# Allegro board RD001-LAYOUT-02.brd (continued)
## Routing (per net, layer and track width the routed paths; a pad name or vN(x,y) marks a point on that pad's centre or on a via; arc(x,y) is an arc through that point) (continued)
SIGN322: length 40.1
  TOP w0.3: 147.27,102.56 147.94,102.56 150.5,100 152.8,100 v2(153.2,100.4)
  TOP w0.55: IC5.6 147.27,102.56
  BOTTOM w0.3: 167.66,113 169.4,113 169.81,113.05 ; v2(153.2,100.4) 153.2,103.7 157,107.5 157,110.8 157.8,111.6 169.8,111.6 170,111.8 170,112.33 ; 167.43,113.23 167.43,114.7 167.37,114.76 166.85,115.3
  BOTTOM w0.55: 169.81,113.05 D22.C 170,112.33
  BOTTOM w0.8: 167.43,113.23 D46.A 167.66,113
  BOTTOM w1.1: D47.C 166.85,115.3
SIGN323: length 2.5
  BOTTOM w0.3: 163.2,113 164.77,113
  BOTTOM w0.92: R136.1 163.2,113
  BOTTOM w1.1: 164.77,113 D46.C
SIGN324: length 1.5
  BOTTOM w0.3: 163.16,115.3 164.29,115.3
  BOTTOM w0.8: 164.29,115.3 D47.A
  BOTTOM w0.92: R137.1 163.16,115.3
SIGN325: length 12.3
  TOP w0.3: 163.29,71.15 164.15,71.15 164.6,70.7 165.75,70.7 ; D44.A 164.97,67.69 164.97,66.47 162.64,64.14 162.64,63.77 ; 166.12,70.42 165.78,69.67 165.78,68.73
  TOP w0.55: 162.64,62.95 IC4.6 162.64,63.77 ; 163.29,71.15 D25.C
  TOP w0.8: D44.A 165.78,68.73
  TOP w1.1: 165.75,70.7 D45.C 166.12,70.42
SIGN326: length 1.6
  TOP w0.3: 168.29,70.7 168.81,70.7 169.5,70.8
  TOP w0.8: D45.A 168.29,70.7
  TOP w0.92: 169.5,70.8 R135.1
SIGN327: length 2
  TOP w0.3: 168.33,68.5 169.6,68.5
  TOP w0.92: 169.6,68.5 R134.1
  TOP w1.1: D44.C 168.33,68.5
SIGN336: length 2.4
  BOTTOM w0.3: 233,91.5 234.6,91.5
  BOTTOM w0.92: 234.6,91.5 R20.1
  BOTTOM w1.1: D53.C 233,91.5
SIGN337: length 1.6
  BOTTOM w0.3: 233.44,93.8 234.73,93.8
  BOTTOM w0.8: D54.A 233.44,93.8
  BOTTOM w0.92: 234.73,93.8 R213.1
SIGN338: length 3.6
  BOTTOM w0.3: 232.75,108.4 234.6,108.4 234.85,108.65 234.85,109.31
  BOTTOM w0.92: 234.85,109.31 R18.1
  BOTTOM w1.1: D51.C 232.75,108.4
SIGN339: length 2.6
  BOTTOM w0.3: R212.1 234.2,112 233.32,111.12 D52.A
SIGN340: length 52.2
  TOP w0.3: 233.47,117.42 233.47,117.89 v2(233.5,118.3) ; 233.88,123.31 234.44,123.31 v2(234.7,123.05) ; v2(213.1,121.6) TP21.1
  TOP w0.5: Q12.4 233.47,117.42 ; Q11.4 233.88,123.31
  CONDUCTIVE4 w0.2: v2(234.7,123.05) 234.2,123.55 215.05,123.55 v2(213.1,121.6)
  CONDUCTIVE4 w0.6: v2(233.5,118.3) 233.5,121.85 v2(234.7,123.05) ; v2(233.5,118.3) 236.65,118.3 v2(237.15,118.8) ; v2(233.5,118.3) 233.5,114.15 234.35,113.3 v2(238.3,113.3)
  BOTTOM w0.3: R216.1 v2(237.15,118.8) ; 237.55,109.31 237.55,108.61 R19.2 ; v2(238.3,113.3) 237.98,112.98 237.55,112.44
  BOTTOM w0.5: 237.55,111.34 237.55,110.09
  BOTTOM w0.92: 237.55,110.09 R18.2 237.55,109.31 ; 237.55,111.34 R212.2 237.55,112.44
SIGN341: length 2.4
  BOTTOM w0.3: 224.6,39.3 224.6,37.78
  BOTTOM w0.92: R24.1 224.6,39.3
  BOTTOM w1.1: 224.6,37.78 D57.C
SIGN342: length 1.5
  BOTTOM w0.3: 222.3,39.35 222.3,38.25
  BOTTOM w0.8: 222.3,38.25 D58.A
  BOTTOM w0.92: R215.1 222.3,39.35
SIGN343: length 45.2
  TOP w0.3: v2(243.85,68.9) 241.9,68.9 ; v2(231.6,74.2) 233.22,74.2 233.47,73.95 233.47,73.39
  TOP w0.5: 233.47,73.39 Q7.4
  TOP w2.1: 241.9,68.9 TP22.1
  CONDUCTIVE4 w0.6: v2(243.96,60.95) 244.9,61.89 244.9,67.85 v2(243.85,68.9) 242.65,70.1 v2(237.15,70.1) 233.9,70.1 231.6,72.4 v2(231.6,74.2) 225.95,79.85 v2(225.95,79.95)
  BOTTOM w0.3: 242.55,64.43 242.55,63.27 ; 236.41,70.1 v2(237.15,70.1) ; 242.71,62.7 243.4,62.7 243.72,62.38 R22.2 ; v2(225.95,79.95) 225.97,80.36 225.97,81.11 ; v2(243.96,60.95) 243.96,61.72
  BOTTOM w0.5: Q8.4 225.97,81.11
  BOTTOM w0.72: R218.1 236.41,70.1 ; 243.96,61.72 R22.2
  BOTTOM w0.92: 242.71,62.7 R23.2 242.55,63.27 ; R214.2 242.55,64.43
SIGN344: length 2.5
  BOTTOM w0.3: 238.03,62.7 239.6,62.7
  BOTTOM w0.92: 239.6,62.7 R23.1
  BOTTOM w1.1: D55.C 238.03,62.7
SIGN345: length 1.5
  BOTTOM w0.3: 238.51,65 239.64,65
  BOTTOM w0.8: D56.A 238.51,65
  BOTTOM w0.92: 239.64,65 R214.1
SIGN351: length 1.8
  BOTTOM w0.3: 233.8,119.5 234.26,119.5 R216.2
  BOTTOM w0.5: Q25.4 233.8,119.5
SIGN352: length 1.8
  BOTTOM w0.3: 233.8,100.8 234.16,100.8 R217.2
  BOTTOM w0.5: Q14.4 233.8,100.8
SIGN353: length 1.8
  BOTTOM w0.3: 233.8,69.39 234.25,69.39 R218.2
  BOTTOM w0.5: Q28.4 233.8,69.39
SIGN354: length 1.5
  BOTTOM w0.3: 233.98,53.8 234.36,53.8 234.9,53.8
  BOTTOM w0.5: Q10.4 233.98,53.8
  BOTTOM w0.72: 234.9,53.8 R219.2
SIGN355: length 142.1
  BOTTOM w1: D19.C 158.8,93 157.2,91.4 150,91.4 ; 150,91.4 149.05,90.45 ; 150,91.4 149.05,91.4 147.95,92.5 ; 150,91.4 149.05,92.35
  BOTTOM w3: Q5.D 142.95,115.25 145.85,112.35 145.85,96.75 147.95,94.65 Q3.D 147.95,77.05 151.09,73.91 155.46,73.91 156.96,72.41 167.72,72.41 171.15,68.98 171.15,51.92 189.02,34.05 T4.1
SIGN356: length 7.5
  BOTTOM w0.45: 221.6,22.69 221.6,21.32 D14.A ; T4.5 217.44,21.3 220.93,21.3
  BOTTOM w0.55: D14.A 220.93,21.3
  BOTTOM w0.72: R9.2 221.6,22.69
SIGN361:
  vias: v5(222.55,83.2) v5(230.05,71.3) v5(230.05,71.3)
SIGN364: length 52.2
  TOP w0.15: 76.1,51.7 R138.1 ; L12.1 106.6,32.2 ; 96.72,49 95.92,49.8 IC20.4 ; C64.2 102.35,42.8
  TOP w5: 76.1,51.7 78.54,51.7 83.24,47 88.58,47 90.58,49 96.72,49 102.35,43.37 102.35,36.45 106.6,32.2
SIGN366: length 5.3
  TOP w0.5: 129.6,64.13 129.6,66.25 HS1.1
  TOP w0.72: R220.2 129.6,64.13
SIGN369: length 6
  TOP w0.45: R221.2 166.46,42.7 HS2.1
SIGN371: length 5.3
  TOP w0.5: HS3.1 117.3,45.15 117.3,43.03
  TOP w0.72: R222.2 117.3,43.03
SIGN373: length 6.4
  TOP w0.5: 173.7,89.67 173.7,87.4 HS4.1
  TOP w0.72: R223.2 173.7,89.67
VREF: length 66.1
  TOP w0.45: v2(258.6,17.5) v2(259.85,17.5) 259.85,13.61 259.24,13 259.24,11.87
  TOP w0.5: 259.38,11.6 260.6,11.6 261.2,11 v2(261.2,10.2) v2(261.2,8.9) 261.2,8.6 260.6,8 259.45,8
  TOP w0.72: 259.24,11.87 R207.2 259.38,11.6 ; R58.2 259.45,8
  CONDUCTIVE3 w1: 245.9,7.3 245.9,7.9 ; 245.9,7.3 245.3,7.9 ; 245.9,7.3 245.9,6.35 244.65,5.1 v2(244.3,5.1) ; 245.9,7.9 245.9,8.5 ; 245.9,7.9 245.3,7.9 ; v2(244.3,7.9) 245.3,7.9 ; 245.3,7.9 245.9,8.5 ; 245.9,8.5 245.9,12.8 248.95,15.85 255.35,15.85 257,17.5 v2(258.6,17.5) ; 259.85,16.25 v2(259.85,17.5) v2(258.6,17.5) ; 259.85,16.25 v2(258.6,17.5) ; 259.85,16.25 259.85,14.05 261.2,12.7 v2(261.2,10.2) v2(261.2,8.9)
  BOTTOM w0.3: R57.2 259.84,10.2 v2(261.2,10.2) v2(261.2,8.9) 261.2,7.95 ; R210.2 v2(244.3,5.1) ; R211.2 v2(244.3,7.9)
  BOTTOM w0.45: 255.06,16.31 255.06,16.76 C99.2 254.78,17.55 256.6,17.55 257.13,17.44 ; v2(259.85,17.5) v2(258.6,17.5) 258.19,17.44 257.46,17.44
  BOTTOM w0.6: 255.06,16.31 IC10.1
  BOTTOM w0.72: 257.46,17.44 R44.2 257.13,17.44 ; 261.2,7.95 R62.2
VREF_PFC: length 40
  TOP w0.3: 154.32,3.64 154.86,3.6 v2(155.4,3.6)
  TOP w0.72: 154.32,3.64 R177.2
  CONDUCTIVE3 w0.5: v2(146.05,4.95) v2(147.3,4.95) 154.05,4.95 v2(155.4,3.6) 156.75,4.95 156.75,15.15 154.65,17.25 v2(153.9,17.25)
  BOTTOM w0.3: R171.2 157.39,17.25 v2(153.9,17.25) ; v2(147.3,4.95) 147.67,5.12 148.26,5.12 ; v2(155.4,3.6) 154.76,3.6 R97.2 ; C42.2 149.15,5.88 149.82,5.88
  BOTTOM w0.4: 149.82,5.88 IC3.13
  BOTTOM w0.45: 148.26,5.12 C42.2
  BOTTOM w0.5: v2(147.3,4.95) v2(146.05,4.95)

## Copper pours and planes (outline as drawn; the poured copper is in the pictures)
P12V on BOTTOM: 273.7,55.25 268.82,60.13 268.79,60.18 268.77,60.24 268.77,68.75 268.82,68.86 268.93,68.9 300.24,68.9 300.3,68.89 300.34,68.86 301.86,67.34 301.89,67.3 301.9,67.24 301.9,40.22 301.89,40.15 301.81,40.01 301.71,39.91 301.51,39.73 301.35,39.55 301.01,38.35 301.55,37.23 301.55,37.22 303.19,35.59 303.32,35.51 303.4,35.5 303.7,35.5 303.85,35.46 303.96,35.35 304,35.2 303.96,35.05 303.85,34.94 303.7,34.9 301.56,34.9 301.5,34.91 301.46,34.94 300.73,35.67 300.46,35.83 300.3,35.85 293.96,35.85 293.79,35.82 293.64,35.72 292.87,34.94 292.82,34.91 292.76,34.9 289.9,34.9 289.75,34.94 289.64,35.05 289.6,35.2 289.6,36.48 289.56,36.63 289.51,36.69 286.29,39.91 286.19,39.98 286.08,40 273.85,40 273.74,40.04 273.7,40.15 ; 18 cut-outs
P12V on CONDUCTIVE3: 272.4,68.8 272.43,68.87 272.5,68.9 300.24,68.9 300.3,68.89 300.34,68.86 301.86,67.34 301.89,67.29 301.9,67.24 301.9,41.76 301.89,41.7 301.86,41.66 300.24,40.04 300.19,40.01 300.14,40 276.86,40 276.8,40.01 276.76,40.04 274.23,42.57 274.21,42.6 274.2,42.64 274.2,56.55 272.43,58.32 272.41,58.35 272.4,58.39 ; 3 cut-outs
VCC3R3_1 on TOP: 205.04,14.6 204.93,14.64 204.89,14.75 204.89,16.19 204.9,16.25 204.93,16.29 205.34,16.71 205.39,16.74 205.45,16.75 206.45,16.75 206.56,16.71 206.6,16.6 206.6,14.75 206.56,14.64 206.45,14.6
VCC12R0_1 on CONDUCTIVE4: 208.05,6.7 207.98,6.73 207.95,6.8 207.95,7.46 207.96,7.5 207.98,7.53 209.32,8.87 209.35,8.89 209.39,8.9 211.25,8.9 211.32,8.87 211.35,8.8 211.35,6.8 211.32,6.73 211.25,6.7
VCC12R0_2 on TOP: 230.55,89.25 230.43,89.27 230.33,89.35 230.3,89.39 230.29,89.45 230.29,90.6 230.33,90.75 230.44,90.86 230.59,90.9 231.8,90.9 231.95,90.86 232.06,90.75 232.1,90.6 232.1,89.55 232.06,89.4 231.95,89.29 231.8,89.25
VCC12R0_2 on TOP: 279.25,4.2 279.1,4.24 278.99,4.35 278.95,4.5 278.95,5.75 278.99,5.9 279.1,6.01 279.25,6.05 281.64,6.05 281.74,6.03 281.82,5.98 281.88,5.89 281.9,5.79 281.9,4.52 281.89,4.45 281.81,4.31 281.79,4.29 281.73,4.24 281.58,4.2
VCC12R0_2 on CONDUCTIVE3: 279.29,3.95 279.25,3.96 279.22,3.98 277.64,5.56 277.57,5.62 277.48,5.64 277.42,5.68 277.4,5.74 277.4,5.95 277.44,6.1 277.55,6.21 277.7,6.25 280.85,6.25 281,6.21 281.11,6.1 281.15,5.95 281.15,4.25 281.11,4.1 281,3.99 280.85,3.95
CONN002 on TOP: 180.75,71.2 184.75,71.2
CONN002 on TOP: 140.91,76.8 140.91,82.2 144.09,82.2 144.09,76.8
CONN002 on BOTTOM: 142.99,76.8 142.96,76.81 142.93,76.82 140.93,78.82 140.92,78.84 140.91,78.87 140.91,82.12 140.93,82.18 140.99,82.2 144.01,82.2 144.07,82.18 144.09,82.12 144.09,76.88 144.07,76.82 144.01,76.8
CONN002 on CONDUCTIVE4: 163.6,77 163.45,77.04 163.34,77.15 163.3,77.3 163.3,79.5 162.2,82.01 159.61,82.89 159.59,82.89 159.45,82.9 159.3,82.9 148.15,82.9 148.1,82.9 145.6,81.96 144.55,79.5 144.55,77.9 144.51,77.75 144.4,77.64 144.25,77.6 140.95,77.6 140.8,77.64 140.69,77.75 140.65,77.9 140.65,82.67 140.66,82.7 140.68,82.74 147.25,89.31 147.32,89.36 147.47,89.4 154.9,89.4 161.26,95.76 161.32,95.81 161.47,95.85 167.38,95.85 167.45,95.84 167.59,95.76 167.91,95.44 167.96,95.38 168,95.23 168,81.46 168,81.43 167.55,80.5 167.4,79.5 167.4,77.3 167.36,77.15 167.25,77.04 167.1,77
CONN003 on TOP: 180.75,56.1 184.75,56.1
CONN003 on BOTTOM: 179.75,54.1 179.75,58.1 184.75,58.1 184.75,54.1
CONN003 on BOTTOM: 179.75,92 179.75,96 184.75,96 184.75,92
CONN004 on TOP (solid shape): 270.8,55.91 271.29,55.78 271.75,55.56 272.16,55.27 272.52,54.91 272.81,54.5 273.03,54.04 273.16,53.55 273.2,53.05 273.2,47.55 273.16,47.05 273.03,46.56 272.81,46.1 272.52,45.69 272.16,45.33 271.75,45.04 271.29,44.82 270.8,44.69 270.3,44.65 269.8,44.69 269.31,44.82 268.85,45.04 268.44,45.33 268.08,45.69 267.79,46.1 267.57,46.56 267.44,47.05 267.4,47.55 267.4,53.05 267.44,53.55 267.57,54.04 267.79,54.5 268.08,54.91 268.44,55.27 268.85,55.56 269.31,55.78 269.8,55.91 270.3,55.95
CONN004 on TOP (solid shape): 275.3,107.51 275.79,107.38 276.25,107.16 276.66,106.87 277.02,106.51 277.31,106.1 277.53,105.64 277.66,105.15 277.7,104.65 277.7,99.15 277.66,98.65 277.53,98.16 277.31,97.7 277.02,97.29 276.66,96.93 276.25,96.64 275.79,96.42 275.3,96.29 274.8,96.25 274.3,96.29 273.81,96.42 273.35,96.64 272.94,96.93 272.58,97.29 272.29,97.7 272.07,98.16 271.94,98.65 271.9,99.15 271.9,104.65 271.94,105.15 272.07,105.64 272.29,106.1 272.58,106.51 272.94,106.87 273.35,107.16 273.81,107.38 274.3,107.51 274.8,107.55
CONN004 on BOTTOM (solid shape): 270.8,55.91 271.29,55.78 271.75,55.56 272.16,55.27 272.52,54.91 272.81,54.5 273.03,54.04 273.16,53.55 273.2,53.05 273.2,47.55 273.16,47.05 273.03,46.56 272.81,46.1 272.52,45.69 272.16,45.33 271.75,45.04 271.29,44.82 270.8,44.69 270.3,44.65 269.8,44.69 269.31,44.82 268.85,45.04 268.44,45.33 268.08,45.69 267.79,46.1 267.57,46.56 267.44,47.05 267.4,47.55 267.4,53.05 267.44,53.55 267.57,54.04 267.79,54.5 268.08,54.91 268.44,55.27 268.85,55.56 269.31,55.78 269.8,55.91 270.3,55.95
CONN004 on BOTTOM (solid shape): 275.3,107.51 275.79,107.38 276.25,107.16 276.66,106.87 277.02,106.51 277.31,106.1 277.53,105.64 277.66,105.15 277.7,104.65 277.7,99.15 277.66,98.65 277.53,98.16 277.31,97.7 277.02,97.29 276.66,96.93 276.25,96.64 275.79,96.42 275.3,96.29 274.8,96.25 274.3,96.29 273.81,96.42 273.35,96.64 272.94,96.93 272.58,97.29 272.29,97.7 272.07,98.16 271.94,98.65 271.9,99.15 271.9,104.65 271.94,105.15 272.07,105.64 272.29,106.1 272.58,106.51 272.94,106.87 273.35,107.16 273.81,107.38 274.3,107.51 274.8,107.55
CONN004 on TOP: outline of 190 points within 251.6,44.65 303.5,123.18
CONN004 on BOTTOM: outline of 197 points within 251,44.65 298.36,123.15
CONN004 on CONDUCTIVE3: 258.29,44.1 258.25,44.11 258.22,44.13 253.53,48.82 253.51,48.85 253.5,48.89 253.5,114.05 251.63,115.92 251.61,115.95 251.6,115.99 251.6,123.1 251.63,123.17 251.7,123.2 258.16,123.2 258.2,123.19 258.23,123.17 265.4,116 294.96,116 295,115.99 295.03,115.97 297.47,113.53 297.49,113.5 297.5,113.46 297.5,84 298.92,82.58 298.94,82.55 298.95,82.51 298.95,73 298.92,72.93 298.85,72.9 273.44,72.9 273.4,72.91 273.37,72.93 271.7,74.6 271.67,74.67 271.67,84.9 271.64,84.97 271.57,85 270.62,85 270.55,84.97 270.52,84.9 270.52,57.1 270.56,56.95 270.61,56.89 272.71,54.79 272.76,54.73 272.8,54.58 272.8,44.4 272.76,44.25 272.65,44.14 272.5,44.1
FG1 on BOTTOM: 27.31,33.8 27.25,33.81 27.21,33.84 23.94,37.1 23.91,37.15 23.9,37.21 23.9,40.19 23.9,40.21 23.92,40.22 24.73,41.02 25.39,41.95 25.4,41.96 33.94,50.51 33.99,50.54 34.05,50.55 40.49,50.55 40.55,50.54 40.59,50.51 42.86,48.24 42.89,48.2 42.9,48.14 42.9,44.03 42.89,43.98 42.86,43.93 32.77,33.84 32.72,33.81 32.66,33.8
FG2 on TOP: 4.5,7.35 4.54,7.46 4.65,7.5 9.58,7.5 9.65,7.49 9.79,7.41 12.91,4.29 12.96,4.23 13,4.08 13,3.56 12.99,3.5 12.96,3.46 10.09,0.59 10.03,0.54 9.88,0.5 6,0.5 5.41,0.62 4.94,0.94 4.61,1.44 4.5,2 ; 1 cut-out
FG5 on BOTTOM: 197.02,0.5 196.95,0.51 196.81,0.59 195.79,1.61 195.74,1.67 195.7,1.82 195.7,2.58 195.71,2.65 195.79,2.79 196.91,3.91 196.97,3.96 197.12,4 197.85,4 197.96,3.96 198,3.86 200.5,1.5 203,3.86 203.04,3.96 203.15,4 203.85,4 203.96,3.96 204,3.85 204,3.39 203.98,3.32 203.87,2.81 203.8,2 203.81,1.7 203.81,0.65 203.77,0.54 203.66,0.5
FG7 on BOTTOM: 296.2,119.58 296.24,119.68 296.35,119.72 297,119.72 297.15,119.88 297.2,119.91 297.26,119.92 298.52,119.92 298.67,119.96 298.73,120.01 298.87,120.15 298.95,120.29 298.96,120.36 298.96,122.42 298.97,122.48 299,122.52 300.89,124.41 300.95,124.46 301.1,124.5 304.5,124.5 305.56,124.06 306,123 306,119.88 305.99,119.81 305.91,119.67 305.58,119.34 302.73,117.51 299.66,118.96 296.35,118.96 296.24,119 296.2,119.11 ; 1 cut-out
INPUT12V_2 on TOP: 284.86,0.5 284.8,0.51 284.76,0.54 282.54,2.76 282.49,2.82 282.45,2.97 282.45,5.6 282.49,5.75 282.6,5.86 282.75,5.9 284.98,5.9 285.05,5.89 285.19,5.81 287.66,3.34 287.69,3.3 287.7,3.24 287.7,0.92 287.69,0.85 287.61,0.71 287.44,0.54 287.4,0.51 287.34,0.5
LGND on TOP: outline of 87 points within 226.85,63.15 240.5,82.55 ; 1 cut-out
LGND on TOP: 232.05,48.45 231.94,48.49 231.9,48.6 231.9,52.25 231.24,52.91 231.1,52.99 231.03,53 230.45,53 230.34,53.04 230.3,53.15 230.3,53.3 230.34,53.45 230.45,53.56 230.6,53.6 234.44,53.6 234.52,53.59 234.65,53.51 234.89,53.28 234.91,53.24 234.94,53.17 234.95,53.1 234.95,52.82 234.94,52.75 234.86,52.61 234.19,51.94 234.11,51.8 234.1,51.73 234.1,48.6 234.06,48.49 233.95,48.45
LGND on TOP: outline of 159 points within 232.9,40 306,124.5 ; 1 cut-out
LGND on BOTTOM: 293.86,35.51 293.9,35.54 293.96,35.55 300.3,35.55 300.42,35.53 302.68,33.3 304.11,31.87 304.14,31.82 304.15,31.76 304.15,16.09 304.14,16.03 304.11,15.98 298.99,10.86 298.91,10.73 298.9,10.65 298.9,5.94 298.89,5.88 298.86,5.83 298.78,5.75 298.62,5.48 298.6,5.33 298.6,4.9 298.56,4.79 298.45,4.75 296.26,4.75 296.2,4.76 296.16,4.79 295.84,5.11 295.7,5.19 295.63,5.2 282.72,5.2 282.65,5.21 282.51,5.29 280.95,6.85 276.07,6.85 276,6.86 275.86,6.94 273.84,8.96 273.81,9 273.8,9.06 273.8,35.25 273.84,35.4 273.95,35.51 274.1,35.55 288.9,35.55 289.05,35.51 289.16,35.4 289.2,35.25 289.2,35.07 289.24,34.92 289.29,34.86 289.37,34.78 289.38,34.77 289.51,34.66 289.67,34.62 289.82,34.61 289.9,34.6 292.76,34.6 292.94,34.63 293.08,34.73 ; 1 cut-out
LGND on BOTTOM: 234.81,43.1 234.75,43.11 234.71,43.14 234.44,43.41 234.39,43.47 234.35,43.62 234.35,47.97 234.24,48.24 233.97,48.34 233.05,48.34 232.94,48.39 232.9,48.49 232.9,51.89 232.91,51.95 232.94,51.99 233.21,52.26 233.25,52.29 233.31,52.3 235.93,52.3 235.96,52.3 236,52.28 236.65,52.39 236.77,53.05 236.76,53.14 236.8,53.22 236.87,53.34 236.9,53.48 236.9,54.12 236.79,54.39 236.53,54.5 234.36,54.5 234.3,54.51 234.26,54.54 234,54.8 233.05,54.8 232.94,54.84 232.9,54.95 232.9,57.88 232.94,57.98 233.03,58.03 233.47,58.36 233.43,58.91 233.41,59.01 233.45,59.1 235.91,61.56 235.97,61.61 236.12,61.65 239.16,61.65 239.2,61.64 239.35,61.57 239.47,61.55 240.24,61.55 240.35,61.57 240.5,61.64 240.54,61.65 241.3,61.65 241.45,61.61 241.56,61.5 241.6,61.35 241.6,47.22 241.59,47.15 241.51,47.01 237.64,43.14 237.6,43.11 237.54,43.1
LGND on BOTTOM: outline of 103 points within 225.4,68 242.45,85.3
LGND on BOTTOM: outline of 126 points within 232.9,40.23 305,124.5 ; 7 cut-outs
LGND on BOTTOM: 238.75,110.85 238.64,110.89 238.6,111 238.6,112.73 238.61,112.8 238.66,112.85 238.84,113.49 238.3,113.88 236.65,113.88 236.54,113.92 236.5,114.03 236.5,115.15 236.54,115.26 236.65,115.3 239.49,115.3 239.55,115.29 239.59,115.26 240.16,114.69 240.19,114.65 240.2,114.59 240.2,111 240.16,110.89 240.05,110.85
LGND on BOTTOM: 234.86,101.05 234.8,101.06 234.76,101.09 234.05,101.8 233.05,101.8 232.94,101.84 232.9,101.95 232.9,104.99 232.97,105.12 233.11,105.13 233.15,105.11 233.96,105.34 233.67,106.13 233.65,106.14 233.4,106.22 233.14,106.19 232.96,106.24 232.98,106.43 233.61,107.06 233.65,107.09 233.71,107.1 237.4,107.1 239.06,108.76 239.1,108.79 239.16,108.8 240.45,108.8 240.56,108.76 240.6,108.65 240.6,101.2 240.56,101.09 240.45,101.05
LGND on CONDUCTIVE2, CONDUCTIVE5: 219.64,18.4 219.6,18.41 219.57,18.43 218.73,19.27 218.71,19.3 218.7,19.34 218.7,32.55 218.3,32.95 215.79,32.95 215.01,33.27 214.69,34.05 214.69,36.26 214.7,36.3 214.72,36.33 215.16,36.77 215.19,36.79 215.23,36.8 216.9,36.8 217.6,37.5 217.6,124.4 217.63,124.47 217.7,124.5 304.5,124.5 305.56,124.06 306,123 306,12.46 305.96,12.31 305.85,12.2 305.7,12.16 302.75,12.16 301.3,11.3 301.35,9.62 301.35,9.53 301.28,9.47 298.13,7.5 296.9,4 296.9,0.8 296.86,0.65 296.75,0.54 296.6,0.5 236.6,0.5 236.53,0.53 236.5,0.6 236.5,10.3 234.13,16.03 228.4,18.4 ; 4 cut-outs
PFC_OUT on TOP, BOTTOM: 133.88,52.36 133.88,56.26 136.48,56.26 136.48,52.36
PFC_OUT on TOP, BOTTOM: 98.43,119.78 98.43,124.03 100.97,124.03 100.97,119.78
PFC_OUT on BOTTOM: 165.08,52.36 165.08,56.26 167.68,56.26 167.68,52.36
PN on TOP: 158.31,76.8 158.31,82.2 161.49,82.2 161.49,76.8
PN on TOP: 164.71,119.1 164.71,124.5 167.89,124.5 167.89,119.1
PN on TOP: 164.1,60.1 163.99,60.14 163.95,60.25 163.91,60.46 163.77,60.69 163.76,60.74 163.76,61.59 163.8,61.7 163.91,61.74 164.9,61.74 164.97,61.77 165,61.84 165,62.15 165.04,62.26 165.15,62.3 165.54,62.3 165.6,62.29 165.64,62.26 165.75,62.15 166.3,62.15 166.45,62.11 166.56,62 166.6,61.85 166.6,61.3 166.64,61.15 166.75,61.04 166.9,61 170.35,61 170.5,60.96 170.61,60.85 170.65,60.7 170.65,60.4 170.61,60.25 170.5,60.14 170.35,60.1
PN on TOP: 141.21,51.5 141.21,56.9 144.39,56.9 144.39,51.5
PN on TOP: 143,95 142.9,95.04 142.85,95.13 142.13,96.87 140.68,98.08 140.62,98.14 140.6,98.21 140.6,101.15 140.64,101.26 140.75,101.3 144.6,101.3 144.86,101.56 144.9,101.59 144.96,101.6 145.05,101.6 145.16,101.56 145.2,101.45 145.2,100.5 145.5,100.2 145.75,100.2 145.86,100.16 145.9,100.05 145.9,99.75 145.86,99.64 145.75,99.6 144.8,99.6 144.3,99.1 144.3,95.15 144.26,95.04 144.15,95
PN on TOP, BOTTOM: 123.43,119.78 123.43,124.03 125.97,124.03 125.97,119.78
PN on BOTTOM: 161.02,100.5 160.95,100.51 160.9,100.56 159.09,101.98 156.85,102.5 155.75,102.5 155.64,102.54 155.6,102.65 155.6,104.2 155.64,104.31 155.75,104.35 160.19,104.35 160.25,104.34 160.29,104.31 162.06,102.54 162.09,102.5 162.1,102.44 162.1,100.65 162.06,100.54 161.95,100.5
PN on BOTTOM: 166.09,118.88 166.03,118.93 165.86,119.1 164.71,119.1 164.71,124.5 167.89,124.5 167.89,119.1 166.77,119.1 166.6,118.93 166.54,118.89 166.39,118.84 166.21,118.84 166.17,118.85
PN on BOTTOM: 110.01,51.5 110.01,56.9 113.19,56.9 113.19,51.5
PN on CONDUCTIVE2: outline of 120 points within 82.25,0.5 228.5,124.5 ; 22 cut-outs
PN on CONDUCTIVE5: outline of 121 points within 82.25,0.5 228.5,124.5 ; 22 cut-outs
SIG2 on BOTTOM: 34.75,22.5 34.64,22.54 34.6,22.65 34.6,28.55 34.64,28.66 34.75,28.7 38.35,28.7 38.46,28.66 38.5,28.55 38.5,23.86 38.49,23.8 38.46,23.76 37.24,22.54 37.2,22.51 37.14,22.5
SIG2 on BOTTOM: 37.55,1.5 37.44,1.54 37.4,1.65 37.4,4.1 37.44,4.21 37.55,4.25 42,4.25 42.11,4.21 42.15,4.1 42.15,1.65 42.11,1.54 42,1.5
SIG6 on TOP: 116.56,92 116.5,92.01 116.46,92.04 115.44,93.06 115.41,93.1 115.4,93.16 115.4,96.85 115.44,96.96 115.55,97 120.25,97 120.36,96.96 120.4,96.85 120.4,93.46 120.39,93.4 120.36,93.36 119.04,92.04 119,92.01 118.94,92
SIG6 on TOP, BOTTOM: 115.93,119.78 115.93,124.03 118.47,124.03 118.47,119.78
SIG8 on TOP, BOTTOM: 108.43,119.78 108.43,124.03 110.97,124.03 110.97,119.78
SIG8 on BOTTOM: 77.02,93.25 76.95,93.26 76.81,93.34 76.54,93.61 76.49,93.67 76.45,93.82 76.45,96.15 76.49,96.3 76.6,96.41 76.75,96.45 78.85,96.45 79,96.41 79.11,96.3 79.15,96.15 79.15,93.55 79.11,93.4 79,93.29 78.85,93.25
SIG11 on BOTTOM: 141.07,66.9 141,66.91 140.86,66.99 139.29,68.56 139.24,68.62 139.2,68.77 139.2,71.1 139.24,71.25 139.35,71.36 139.5,71.4 143.9,71.4 144.05,71.36 144.16,71.25 144.2,71.1 144.2,70.72 144.24,70.57 144.29,70.51 146.21,68.59 146.26,68.53 146.3,68.38 146.3,67.2 146.26,67.05 146.15,66.94 146,66.9
SIG11 on BOTTOM: 137.41,89.51 137.3,89.46 137.19,89.51 133.91,92.79 133.86,92.9 133.91,93.01 136.96,96.06 137,96.09 137.06,96.1 139.44,96.1 139.5,96.09 139.54,96.06 140.46,95.14 140.49,95.1 140.5,95.04 140.5,92.81 140.47,92.73 140.41,92.67 139.42,91.99 138.81,90.95 138.8,90.92 138.78,90.9 138.73,90.84 138.68,90.78
SIG12 on TOP: 128.8,52.36 128.8,56.26 131.4,56.26 131.4,52.36
SIG12 on BOTTOM: 128.8,52.36 128.8,53.88 126.31,56.37 126.26,56.48 128.22,58.49 128.32,58.54 128.43,58.49 130.66,56.26 131.4,56.26 131.4,52.36
SIG12 on BOTTOM: 121.8,66.5 121.69,66.54 121.65,66.65 121.65,67.38 121.62,67.45 121.55,67.47 117.76,67.47 117.7,67.49 117.66,67.52 116.79,68.39 116.74,68.45 116.7,68.6 116.7,73.1 116.74,73.25 116.85,73.36 117,73.4 121.2,73.4 121.45,73.33 121.63,73.15 121.7,72.9 121.7,70.27 121.74,70.12 121.79,70.06 125.09,66.76 125.13,66.59 124.99,66.5
SIG18 on TOP, BOTTOM: 146.66,51.5 146.66,56.9 149.84,56.9 149.84,51.5
SIG82 on TOP: 153.81,119.1 153.81,124.5 156.99,124.5 156.99,119.1
SIG82 on BOTTOM: 155.19,118.88 155.13,118.93 154.96,119.1 153.81,119.1 153.81,124.5 156.99,124.5 156.99,119.1 155.87,119.1 155.7,118.93 155.64,118.89 155.49,118.84 155.31,118.84 155.27,118.85
SIG115 on TOP (solid shape): 224.11,72.66 224.65,72.3 225.03,71.74 225.15,71.1 225.01,70.44 224.65,69.9 224.09,69.52 223.45,69.4 217.55,69.4 216.89,69.54 216.35,69.9 215.97,70.46 215.85,71.1 215.99,71.76 216.35,72.3 216.91,72.68 217.55,72.8 223.45,72.8
SIG115 on BOTTOM (solid shape): 224.11,72.66 224.65,72.3 225.03,71.74 225.15,71.1 225.01,70.44 224.65,69.9 224.09,69.52 223.45,69.4 217.55,69.4 216.89,69.54 216.35,69.9 215.97,70.46 215.85,71.1 215.99,71.76 216.35,72.3 216.91,72.68 217.55,72.8 223.45,72.8
SIG115 on TOP: 222.82,63.1 222.75,63.11 222.61,63.19 216.44,69.36 216.3,69.44 216.23,69.45 216.1,69.45 215.99,69.49 215.95,69.6 215.95,70.53 215.85,71.1 215.95,71.67 215.95,72.5 215.99,72.65 216.1,72.76 216.25,72.8 224.85,72.8 225,72.76 225.11,72.65 225.15,72.5 225.15,69.45 225.19,69.3 225.24,69.24 226.95,67.53 231.75,67.53 231.86,67.48 231.9,67.38 231.9,63.25 231.86,63.14 231.75,63.1
SIG115 on BOTTOM: outline of 81 points within 215.85,40.5 231.9,72.8
SIG124 on TOP: 229.3,90.1 229.15,90.14 229.04,90.25 229,90.4 229,91.18 229.01,91.25 229.09,91.39 229.11,91.41 229.19,91.55 229.2,91.62 229.2,92.95 229.24,93.1 229.35,93.21 229.5,93.25 229.8,93.25 229.95,93.21 230.06,93.1 230.1,92.95 230.1,91.67 230.09,91.6 230.01,91.46 229.79,91.24 229.71,91.1 229.7,91.03 229.7,90.4 229.66,90.25 229.55,90.14 229.52,90.13 229.49,90.12 229.45,90.12
SIG134 on TOP (solid shape): 224.11,110.56 224.65,110.2 225.03,109.64 225.15,109 225.01,108.34 224.65,107.8 224.09,107.42 223.45,107.3 217.55,107.3 216.89,107.44 216.35,107.8 215.97,108.36 215.85,109 215.99,109.66 216.35,110.2 216.91,110.58 217.55,110.7 223.45,110.7
SIG134 on BOTTOM (solid shape): 224.11,110.56 224.65,110.2 225.03,109.64 225.15,109 225.01,108.34 224.65,107.8 224.09,107.42 223.45,107.3 217.55,107.3 216.89,107.44 216.35,107.8 215.97,108.36 215.85,109 215.99,109.66 216.35,110.2 216.91,110.58 217.55,110.7 223.45,110.7
SIG134 on TOP: 223.62,100.5 223.55,100.51 223.41,100.59 222.54,101.46 222.49,101.52 222.45,101.67 222.45,103.53 222.41,103.68 222.36,103.74 221.04,105.06 220.9,105.14 220.83,105.15 217.56,105.15 217.5,105.16 217.46,105.19 216.34,106.31 216.29,106.37 216.25,106.52 216.25,107.9 215.85,109 216.25,110.1 216.25,110.6 216.29,110.75 216.4,110.86 216.55,110.9 231.75,110.9 231.86,110.86 231.9,110.75 231.9,106.62 231.86,106.52 231.75,106.47 229.82,106.47 229.77,106.45 229.75,106.4 229.75,105 229.77,104.95 229.82,104.92 231.75,104.92 231.86,104.88 231.9,104.78 231.9,100.65 231.86,100.54 231.75,100.5
SIG134 on BOTTOM: 226.23,97.1 226.17,97.11 226.12,97.14 224.61,98.65 224.42,98.78 224.2,98.83 220.69,98.83 220.63,98.84 220.58,98.87 216.29,103.16 216.26,103.2 216.25,103.26 216.25,106.3 215.85,106.3 215.85,109 215.95,109.58 216.25,110.1 216.25,110.4 216.29,110.55 216.4,110.66 216.55,110.7 224.75,110.7 224.9,110.66 225.01,110.55 225.05,110.4 225.05,109.57 225.12,109.29 225.15,109 225.15,106.3 225.05,106.3 225.05,106.2 226.35,104.9 231.75,104.9 231.86,104.86 231.9,104.75 231.9,100.62 231.86,100.52 231.75,100.47 229.75,100.47 228.82,99.55 228.82,97.25 228.78,97.14 228.68,97.1
SIG135 on TOP (solid shape): 224.11,115.56 224.65,115.2 225.03,114.64 225.15,114 225.01,113.34 224.65,112.8 224.09,112.42 223.45,112.3 217.55,112.3 216.89,112.44 216.35,112.8 215.97,113.36 215.85,114 215.99,114.66 216.35,115.2 216.91,115.58 217.55,115.7 223.45,115.7
SIG135 on BOTTOM (solid shape): 224.11,115.56 224.65,115.2 225.03,114.64 225.15,114 225.01,113.34 224.65,112.8 224.09,112.42 223.45,112.3 217.55,112.3 216.89,112.44 216.35,112.8 215.97,113.36 215.85,114 215.99,114.66 216.35,115.2 216.91,115.58 217.55,115.7 223.45,115.7
SIG135 on TOP: 217.55,112.3 216.69,112.53 216.07,113.16 215.91,113.26 215.85,113.44 215.85,115.55 215.89,115.66 216,115.7 216.15,115.7 216.22,115.73 216.25,115.8 216.25,119.75 216.25,119.76 216.26,119.83 216.29,119.89 218.46,122.06 218.5,122.09 218.56,122.1 222.05,122.1 223.51,123.56 223.55,123.59 223.61,123.6 231.75,123.6 231.86,123.56 231.9,123.45 231.9,119.33 231.86,119.22 231.75,119.17 229.82,119.17 229.77,119.15 229.75,119.1 229.75,117.7 229.77,117.65 229.82,117.62 231.75,117.62 231.86,117.58 231.9,117.47 231.9,113.3 231.86,113.19 231.75,113.15 231.28,113.15 231.24,113.15 231.18,113.17 229.82,113.17 229.76,113.15 229.72,113.15 224.92,113.15 224.3,112.53 223.45,112.3
SIG135 on BOTTOM: 216.55,112.3 216.4,112.34 216.29,112.45 216.25,112.6 216.25,112.9 215.95,113.42 215.85,114 215.85,116.7 216.25,116.7 216.25,119.73 216.26,119.8 216.34,119.94 219.96,123.56 220,123.59 220.06,123.6 231.75,123.6 231.86,123.56 231.9,123.45 231.9,119.35 231.86,119.24 231.75,119.2 229.45,119.2 228.8,118.55 228.8,115.75 228.76,115.64 228.65,115.6 225.5,115.6 225.15,115.25 225.15,114 225.12,113.71 225.05,113.43 225.05,112.6 225.01,112.45 224.9,112.34 224.75,112.3
SIG138 on BOTTOM: 232.35,115.6 232.24,115.64 232.2,115.75 232.2,117.45 232.24,117.56 232.35,117.6 235.3,117.6 235.41,117.56 235.45,117.45 235.45,115.75 235.41,115.64 235.3,115.6
SIG138 on BOTTOM: 232.35,97.1 232.24,97.14 232.2,97.25 232.2,98.95 232.24,99.06 232.35,99.1 237.45,99.1 237.56,99.06 237.6,98.95 237.6,97.25 237.56,97.14 237.45,97.1 235.49,97.1 235.38,97.12 235.3,97.12 234.3,97.12 234.22,97.12 234.11,97.1
SIG199 on BOTTOM: 74.35,30.75 74.24,30.79 74.2,30.9 74.2,35.34 74.21,35.4 74.24,35.44 75.61,36.81 75.65,36.84 75.71,36.85 77.44,36.85 77.5,36.84 77.54,36.81 78.86,35.49 78.89,35.45 78.9,35.39 78.9,30.9 78.86,30.79 78.75,30.75
SIG200 on BOTTOM: 68.46,6.5 68.4,6.51 68.36,6.54 67.84,7.06 67.81,7.1 67.8,7.16 67.8,12.85 67.84,12.96 67.95,13 72.65,13 72.76,12.96 72.8,12.85 72.8,7.78 72.8,7.74 72.78,7.71 72.53,7.23 72.32,6.73 72.3,6.71 72.28,6.68 72.14,6.54 72.1,6.51 72.04,6.5
SIG200 on BOTTOM: 78.36,16.8 78.3,16.81 78.26,16.84 75.74,19.36 75.71,19.4 75.7,19.46 75.7,23.1 75.74,23.21 75.85,23.25 82.65,23.25 82.76,23.21 82.8,23.1 82.8,19.56 82.79,19.5 82.76,19.46 80.14,16.84 80.1,16.81 80.04,16.8
SIG200 on BOTTOM: 86.56,6.5 86.5,6.51 86.46,6.54 86.32,6.68 86.3,6.71 86.28,6.73 86.11,7.14 85.92,7.53 85.9,7.56 85.9,7.6 85.9,13.65 85.94,13.76 86.05,13.8 90.75,13.8 90.86,13.76 90.9,13.65 90.9,6.96 90.89,6.9 90.86,6.86 90.71,6.71 90.69,6.69 90.66,6.68 90.48,6.6 90.3,6.52 90.27,6.5 90.23,6.5
SIG205 on TOP: 169.21,76.8 169.21,82.2 172.39,82.2 172.39,76.8
SIG249 on TOP: 159.26,119.1 159.26,124.5 162.44,124.5 162.44,119.1
SIG249 on TOP, BOTTOM: 146.81,119.1 146.81,124.5 149.99,124.5 149.99,119.1
SIG249 on CONDUCTIVE3: 156.6,94.51 156.56,94.54 155.54,95.56 155.51,95.61 155.5,95.66 155.5,97.96 155.5,97.98 155.51,98.01 155.71,98.46 155.83,98.95 155.84,98.98 155.86,99.01 157.75,100.9 157.75,100.9 158.34,101.77 158.55,102.8 158.55,108.28 154.01,112.82 154,112.83 153.08,113.54 151.95,113.8 149.82,113.8 149.78,113.81 149.75,113.83 146.83,116.75 146.81,116.78 146.8,116.82 146.8,120.4 146.8,120.43 146.98,121.12 147.04,121.8 147.04,123.25 147.08,123.36 147.19,123.4 150.56,123.4 150.67,123.36 150.71,123.25 150.71,121.8 151.21,119.85 152.57,118.37 157.75,118.37 158.4,119.02 159.21,120.31 159.49,121.8 159.49,123.3 159.53,123.41 159.64,123.45 162.06,123.45 162.17,123.41 162.21,123.3 162.21,121.8 162.24,121.3 162.45,120.44 162.6,120.06 162.6,120.03 162.6,117.45 165.76,114.29 165.86,114.22 165.97,114.2 166.1,114.2 166.31,114.11 166.4,113.9 166.4,97.54 166.39,97.5 166.37,97.47 163.43,94.53 163.4,94.51 163.36,94.5 156.66,94.5
SIGN267 on TOP: 120.91,51.5 120.91,56.9 124.09,56.9 124.09,51.5
SIGN271 on BOTTOM: 176.8,14 176.69,14.01 176.59,14.05 176.52,14.1 176.5,14.18 176.5,14.82 176.5,15.01 176.48,15.19 176.5,15.28 176.56,15.34 176.68,15.38 176.8,15.4 182.49,15.4 182.63,15.31 182.6,15.14 182.24,14.79 181.94,14.44 181.67,14.07 181.61,14.02 181.54,14
SIGN273 on BOTTOM: 246.95,60.85 246.8,60.89 246.69,61 246.65,61.15 246.65,64.88 246.61,65.03 246.56,65.09 245.29,66.36 245.24,66.42 245.2,66.57 245.2,67.13 245.21,67.2 245.29,67.34 248.46,70.51 248.5,70.54 248.56,70.55 252.6,70.55 252.71,70.51 252.75,70.4 252.75,61.75 252.71,61.64 252.6,61.6 248.6,61.6 247.94,60.94 247.88,60.89 247.73,60.85
SIGN273 on BOTTOM: 238.35,66.3 238.2,66.34 238.09,66.45 238.05,66.6 238.05,67 238.09,67.15 238.2,67.26 238.35,67.3 241.7,67.3 241.85,67.26 241.96,67.15 242,67 242,66.6 241.96,66.45 241.85,66.34 241.7,66.3
SIGN273 on BOTTOM: 232.35,65.7 232.24,65.74 232.2,65.85 232.2,67.55 232.24,67.66 232.35,67.7 233.31,67.7 233.35,67.69 233.5,67.67 233.65,67.69 233.69,67.7 233.99,67.7 234.05,67.69 234.09,67.66 234.41,67.34 234.44,67.3 234.45,67.24 234.45,65.85 234.41,65.74 234.3,65.7
SIGN321 on TOP, BOTTOM: 135.91,119.1 135.91,124.5 139.09,124.5 139.09,119.1
SIGN355 on BOTTOM: 147.35,89.05 147.2,89.09 147.09,89.2 147.05,89.35 147.05,94.35 147.09,94.5 147.2,94.61 147.35,94.65 148.8,94.65 148.95,94.61 149.06,94.5 149.1,94.35 149.1,89.35 149.06,89.2 148.95,89.09 148.8,89.05
SIGN355 on BOTTOM: 141.36,119.1 141.36,124.5 144.54,124.5 144.54,119.1
SIGN355 on BOTTOM: 146.36,76.8 146.36,82.2 149.54,82.2 149.54,76.8
SIGN360 on TOP (solid shape): 224.11,57.66 224.65,57.3 225.03,56.74 225.15,56.1 225.01,55.44 224.65,54.9 224.09,54.52 223.45,54.4 217.55,54.4 216.89,54.54 216.35,54.9 215.97,55.46 215.85,56.1 215.99,56.76 216.35,57.3 216.91,57.68 217.55,57.8 223.45,57.8
SIGN360 on TOP (solid shape): 224.11,52.66 224.65,52.3 225.03,51.74 225.15,51.1 225.01,50.44 224.65,49.9 224.09,49.52 223.45,49.4 217.55,49.4 216.89,49.54 216.35,49.9 215.97,50.46 215.85,51.1 215.99,51.76 216.35,52.3 216.91,52.68 217.55,52.8 223.45,52.8
SIGN360 on TOP (solid shape): 230.8,35.91 231.29,35.78 231.75,35.56 232.16,35.27 232.52,34.91 232.81,34.5 233.03,34.04 233.16,33.55 233.2,33.05 233.2,27.55 233.16,27.05 233.03,26.56 232.81,26.1 232.52,25.69 232.16,25.33 231.75,25.04 231.29,24.82 230.8,24.69 230.3,24.65 229.8,24.69 229.31,24.82 228.85,25.04 228.44,25.33 228.08,25.69 227.79,26.1 227.57,26.56 227.44,27.05 227.4,27.55 227.4,33.05 227.44,33.55 227.57,34.04 227.79,34.5 228.08,34.91 228.44,35.27 228.85,35.56 229.31,35.78 229.8,35.91 230.3,35.95
SIGN360 on BOTTOM (solid shape): 224.11,57.66 224.65,57.3 225.03,56.74 225.15,56.1 225.01,55.44 224.65,54.9 224.09,54.52 223.45,54.4 217.55,54.4 216.89,54.54 216.35,54.9 215.97,55.46 215.85,56.1 215.99,56.76 216.35,57.3 216.91,57.68 217.55,57.8 223.45,57.8
SIGN360 on BOTTOM (solid shape): 224.11,52.66 224.65,52.3 225.03,51.74 225.15,51.1 225.01,50.44 224.65,49.9 224.09,49.52 223.45,49.4 217.55,49.4 216.89,49.54 216.35,49.9 215.97,50.46 215.85,51.1 215.99,51.76 216.35,52.3 216.91,52.68 217.55,52.8 223.45,52.8
SIGN360 on BOTTOM (solid shape): 230.8,35.91 231.29,35.78 231.75,35.56 232.16,35.27 232.52,34.91 232.81,34.5 233.03,34.04 233.16,33.55 233.2,33.05 233.2,27.55 233.16,27.05 233.03,26.56 232.81,26.1 232.52,25.69 232.16,25.33 231.75,25.04 231.29,24.82 230.8,24.69 230.3,24.65 229.8,24.69 229.31,24.82 228.85,25.04 228.44,25.33 228.08,25.69 227.79,26.1 227.57,26.56 227.44,27.05 227.4,27.55 227.4,33.05 227.44,33.55 227.57,34.04 227.79,34.5 228.08,34.91 228.44,35.27 228.85,35.56 229.31,35.78 229.8,35.91 230.3,35.95
SIGN360 on TOP: 231.36,24.85 230.3,24.65 229.24,24.85 225.82,24.85 225.75,24.86 225.61,24.94 219.69,30.86 219.66,30.9 219.65,30.96 219.65,36.25 216.34,39.56 216.29,39.62 216.25,39.77 216.25,50 215.85,51.1 216.25,52.2 216.25,55 215.85,56.1 216.25,57.2 216.25,57.5 216.29,57.65 216.4,57.76 216.55,57.8 224.75,57.8 224.9,57.76 225.01,57.65 225.05,57.5 225.05,56.67 225.15,56.1 225.05,55.53 225.05,51.67 225.15,51.1 225.05,50.53 225.05,39.02 225.09,38.87 225.14,38.81 227.81,36.14 227.91,36.07 228.02,36.05 233.15,36.05 233.3,36.01 233.41,35.9 233.45,35.75 233.45,25.15 233.41,25 233.3,24.89 233.15,24.85
SIGN360 on BOTTOM: 215.85,48.4 215.85,51.1 215.99,51.76 216.35,52.3 216.91,52.68 217.55,52.8 223.45,52.8 224.11,52.66 224.65,52.3 225.03,51.74 225.15,51.1 225.15,48.4
SIGN360 on BOTTOM: 230.3,24.65 229.8,24.69 229.31,24.82 228.85,25.04 228.44,25.33 228.08,25.69 227.79,26.1 227.57,26.56 227.44,27.05 227.4,27.55 227.4,33.05 227.44,33.55 227.57,34.04 227.79,34.5 228.08,34.91 228.44,35.27 228.85,35.56 229.31,35.78 229.8,35.91 230.3,35.95 230.8,35.91 231.29,35.78 231.75,35.56 232.16,35.27 232.52,34.91 232.81,34.5 233.03,34.04 233.16,33.55 233.2,33.05 233.2,27.55 233.16,27.05 233.03,26.56 232.81,26.1 232.52,25.69 232.16,25.33 231.75,25.04 231.29,24.82 230.8,24.69
SIGN360 on BOTTOM: 217.55,54.4 216.89,54.54 216.35,54.9 215.97,55.46 215.85,56.1 215.99,56.76 216.35,57.3 216.91,57.68 217.55,57.8 223.45,57.8 224.11,57.66 224.65,57.3 225.03,56.74 225.15,56.1 225.01,55.44 224.65,54.9 224.09,54.52 223.45,54.4
SIGN361 on TOP (solid shape): 224.11,77.66 224.65,77.3 225.03,76.74 225.15,76.1 225.01,75.44 224.65,74.9 224.09,74.52 223.45,74.4 217.55,74.4 216.89,74.54 216.35,74.9 215.97,75.46 215.85,76.1 215.99,76.76 216.35,77.3 216.91,77.68 217.55,77.8 223.45,77.8
SIGN361 on BOTTOM (solid shape): 224.11,77.66 224.65,77.3 225.03,76.74 225.15,76.1 225.01,75.44 224.65,74.9 224.09,74.52 223.45,74.4 217.55,74.4 216.89,74.54 216.35,74.9 215.97,75.46 215.85,76.1 215.99,76.76 216.35,77.3 216.91,77.68 217.55,77.8 223.45,77.8
SIGN361 on TOP: 226.51,69.1 226.45,69.11 226.41,69.14 225.74,69.81 225.69,69.87 225.65,70.02 225.65,73.03 225.61,73.18 225.56,73.24 224.49,74.31 224.35,74.39 224.28,74.4 216,74.4 215.89,74.44 215.85,74.55 215.85,77.65 215.89,77.76 216,77.8 216.15,77.8 216.22,77.83 216.25,77.9 216.25,78.35 216.29,78.46 216.4,78.5 227.3,78.5 227.38,78.49 227.51,78.41 229.44,76.49 229.48,76.43 229.52,76.28 229.53,73.87 229.57,73.72 229.61,73.66 229.66,73.61 229.71,73.57 229.82,73.53 231.6,73.53 231.75,73.48 231.86,73.38 231.9,73.22 231.9,69.4 231.86,69.25 231.75,69.14 231.6,69.1
SIGN361 on BOTTOM: 227.82,65.7 227.75,65.71 227.61,65.79 227.04,66.36 226.99,66.42 226.95,66.57 226.95,72.33 226.91,72.48 226.86,72.54 225,74.4 216.14,74.4 215.94,74.49 215.85,74.69 215.85,74.7 215.85,78.8 216.25,78.8 216.25,83.78 216.26,83.85 216.34,83.99 217.66,85.31 217.72,85.36 217.87,85.4 224.1,85.4 224.25,85.36 224.36,85.25 224.4,85.1 224.4,81.28 224.36,81.12 224.25,81.02 224.1,80.97 222.32,80.97 222.27,80.95 222.25,80.9 222.25,80.02 222.29,79.87 222.34,79.81 222.69,79.46 222.82,79.39 222.9,79.38 226.62,79.38 226.69,79.36 226.83,79.29 229.49,76.63 229.53,76.57 229.57,76.42 229.57,73.82 229.6,73.71 229.71,73.57 229.82,73.53 231.6,73.53 231.75,73.48 231.86,73.38 231.9,73.22 231.9,69.35 231.86,69.2 231.75,69.09 231.6,69.05 231.28,69.05 231.24,69.05 231.18,69.08 229.82,69.08 229.76,69.05 229.72,69.05 229.5,69.05 228.89,68.44 228.81,68.3 228.8,68.23 228.8,66 228.76,65.85 228.65,65.74 228.5,65.7
SIGN362 on TOP (solid shape): 224.11,95.56 224.65,95.2 225.03,94.64 225.15,94 225.01,93.34 224.65,92.8 224.09,92.42 223.45,92.3 217.55,92.3 216.89,92.44 216.35,92.8 215.97,93.36 215.85,94 215.99,94.66 216.35,95.2 216.91,95.58 217.55,95.7 223.45,95.7
SIGN362 on TOP (solid shape): 224.11,90.56 224.65,90.2 225.03,89.64 225.15,89 225.01,88.34 224.65,87.8 224.09,87.42 223.45,87.3 217.55,87.3 216.89,87.44 216.35,87.8 215.97,88.36 215.85,89 215.99,89.66 216.35,90.2 216.91,90.58 217.55,90.7 223.45,90.7
SIGN362 on TOP (solid shape): 235.3,87.51 235.79,87.38 236.25,87.16 236.66,86.87 237.02,86.51 237.31,86.1 237.53,85.64 237.66,85.15 237.7,84.65 237.7,79.15 237.66,78.65 237.53,78.16 237.31,77.7 237.02,77.29 236.66,76.93 236.25,76.64 235.79,76.42 235.3,76.29 234.8,76.25 234.3,76.29 233.81,76.42 233.35,76.64 232.94,76.93 232.58,77.29 232.29,77.7 232.07,78.16 231.94,78.65 231.9,79.15 231.9,84.65 231.94,85.15 232.07,85.64 232.29,86.1 232.58,86.51 232.94,86.87 233.35,87.16 233.81,87.38 234.3,87.51 234.8,87.55
SIGN362 on BOTTOM (solid shape): 224.11,95.56 224.65,95.2 225.03,94.64 225.15,94 225.01,93.34 224.65,92.8 224.09,92.42 223.45,92.3 217.55,92.3 216.89,92.44 216.35,92.8 215.97,93.36 215.85,94 215.99,94.66 216.35,95.2 216.91,95.58 217.55,95.7 223.45,95.7
SIGN362 on BOTTOM (solid shape): 224.11,90.56 224.65,90.2 225.03,89.64 225.15,89 225.01,88.34 224.65,87.8 224.09,87.42 223.45,87.3 217.55,87.3 216.89,87.44 216.35,87.8 215.97,88.36 215.85,89 215.99,89.66 216.35,90.2 216.91,90.58 217.55,90.7 223.45,90.7
SIGN362 on BOTTOM (solid shape): 235.3,87.51 235.79,87.38 236.25,87.16 236.66,86.87 237.02,86.51 237.31,86.1 237.53,85.64 237.66,85.15 237.7,84.65 237.7,79.15 237.66,78.65 237.53,78.16 237.31,77.7 237.02,77.29 236.66,76.93 236.25,76.64 235.79,76.42 235.3,76.29 234.8,76.25 234.3,76.29 233.81,76.42 233.35,76.64 232.94,76.93 232.58,77.29 232.29,77.7 232.07,78.16 231.94,78.65 231.9,79.15 231.9,84.65 231.94,85.15 232.07,85.64 232.29,86.1 232.58,86.51 232.94,86.87 233.35,87.16 233.81,87.38 234.3,87.51 234.8,87.55
SIGN362 on TOP: 235.2,76.08 233.75,76.28 233.47,76.44 233.21,76.64 233.2,76.65 231.19,78.66 231.14,78.72 231.1,78.87 231.1,82.4 230.74,82.76 230.6,82.84 230.53,82.85 226.42,82.85 226.27,82.81 226.21,82.76 225.39,81.94 225.33,81.89 225.18,81.85 218.52,81.85 218.45,81.86 218.31,81.94 216.29,83.96 216.26,84 216.25,84.06 216.25,85.36 216.25,87.9 215.85,89 216.25,90.1 216.25,92.9 215.85,94 216.25,95.1 216.25,95.4 216.29,95.55 216.4,95.66 216.55,95.7 224.9,95.7 225.05,95.66 225.16,95.55 225.2,95.4 225.2,89.87 225.24,89.72 225.29,89.66 226.16,88.79 226.26,88.72 226.37,88.7 234.53,88.7 234.6,88.69 234.74,88.61 236.12,87.23 237.27,86.17 237.7,84.65 237.7,79.15 237.54,78.2 237.08,77.36 237.05,77.3 237.01,77.26 236.7,76.94 236.58,76.82 236.51,76.74
SIGN362 on BOTTOM: 234.8,76.25 234.3,76.29 233.81,76.42 233.35,76.64 232.94,76.93 232.58,77.29 232.29,77.7 232.07,78.16 231.94,78.65 231.9,79.15 231.9,84.65 231.94,85.15 232.07,85.64 232.29,86.1 232.58,86.51 232.94,86.87 233.35,87.16 233.81,87.38 234.3,87.51 234.8,87.55 235.3,87.51 235.79,87.38 236.25,87.16 236.66,86.87 237.02,86.51 237.31,86.1 237.53,85.64 237.66,85.15 237.7,84.65 237.7,79.15 237.66,78.65 237.53,78.16 237.31,77.7 237.02,77.29 236.66,76.93 236.25,76.64 235.79,76.42 235.3,76.29
SIGN362 on BOTTOM: 215.93,86.8 215.87,86.82 215.85,86.88 215.85,88.92 215.85,89 215.99,89.66 216.35,90.2 216.91,90.58 217.55,90.7 223.45,90.7 224.11,90.56 224.65,90.2 225.03,89.64 225.15,89 225.15,88.92 225.15,86.88 225.13,86.82 225.07,86.8
SIGN362 on BOTTOM: 217.55,92.3 216.89,92.44 216.35,92.8 215.97,93.36 215.85,94 215.85,96.7 225.15,96.7 225.15,94 225.01,93.34 224.65,92.8 224.09,92.42 223.45,92.3
SIGN364 on TOP: 73.75,49.2 73.64,49.24 73.6,49.35 73.6,54.05 73.64,54.16 73.75,54.2 77.55,54.2 77.66,54.16 77.7,54.05 77.7,49.35 77.66,49.24 77.55,49.2
SIGN366 on BOTTOM: 130.18,66 130.07,65.95 129.97,66 126.45,69.52 126.4,69.62 126.45,69.73 128.92,72.2 129.03,72.25 129.13,72.2 132.65,68.68 132.7,68.58 132.65,68.47
SIGN369 on BOTTOM: 167.4,40.06 167.29,40.1 167.25,40.21 167.25,42.55 167.29,42.66 167.4,42.7 170.9,42.7 171.01,42.66 171.05,42.55 171.05,40.21 171.01,40.1 170.9,40.06
SIGN371 on BOTTOM: 113.76,46.1 113.65,46.14 113.61,46.25 113.61,49.75 113.65,49.86 113.76,49.9 120.74,49.9 120.85,49.86 120.89,49.75 120.89,46.25 120.85,46.14 120.74,46.1
SIGN373 on BOTTOM: 174.7,84.7 174.59,84.74 174.55,84.85 174.55,88.19 174.59,88.3 174.7,88.34 178.2,88.34 178.31,88.3 178.35,88.19 178.35,84.85 178.31,84.74 178.2,84.7

Small or netless copper shapes (teardrops, artwork), in the pictures only: 7 on TOP, 11 on BOTTOM, 1 on CONDUCTIVE3, 2 on CONDUCTIVE4

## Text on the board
Ref Des/Silkscreen Bottom: 1 | 2 | 6 | 7 | 3 | 4 | 5
Ref Des/Silkscreen Top: S | D | G | 2 | 1 | A | C | 6 | 7 | 3 | 4 | 5 | R | F
SYMBOL-A-1: S | D | G | 2 | 1 | A | C | 6 | 7 | 3 | 4 | 5 | R | F
SYMBOL-A-2: S | D | G | 2 | 1 | 4 | 3 | A | C | 6 | 7 | 5 | F | R | R225 | HS3 | HS1 | SW | HS2 | HS4 | SNB1 | T6-3 | T5-3 | T6-6 | T6-5 | NETA | C79 | FOR CONTINUED PROTECTION AGAINST RISK OF FIRE. | RV1 | F1 | C78 | C54 | C53 | R111 | R110 | C82 | C83 | R121 | C64 | C37 | D33 | T3 | Q1 | R173 | R87 | TP2 | R28 | CSA | R133 | R132 | C7 | D3 | R74 | R109 | D9 | D8 | CSB | TP1 | TP43 | PN | R73 | Q1-G | TP4 | D38 | D39 | T2 | R120 | Q5-G | TP13 | D1 | TP6 | Q3 | C87 | IC2 | C81 | C55 | C86 | GDB | C80 | Q5 | Q3-G | TP11 | C62 | D43 | D42 | D24 | TP5 | GDA | Q2 | D31 | R114 | TP9 | D23 | OUTC1 | D41 | Q4-G | TP12 | TP7 | R126 | B | TP3 | VINAC | Q2-G | Q6-G | TP14 | IC4 | D25 | TP15 | D45 | D44 | D2 | TP8 | Q6 | VSENSE | R115 | R33 | Q4 | R134 | R135 | D36 | D37 | D30 | R72 | R71 | R108 | C1 | HOT. TEST BEFORE | R174 | R198 | TOUCHING ON HEATSINKS | R175 | R176 | TP45 | IC11 | C67 | TP27 | R117 | R130 | CN2 | TP21 | CN3 | T4 | TP29 | TP24 | OUTF | Q11-G | C74 | TP17 | R193 | IC24 | IC23 | TP26 | R191 | TP18 | TP25 | OUTE | TP30 | Q26 | Q27 | IC7 | C61 | C60 | C91 | IC6 | R155 | R163 | Q7 | C88 | C89 | R156 | R166 | R125 | C90 | IC15 | IC16 | Q12 | Q11 | R196 | R151 | R197 | R152 | R128 | TP22 | TP19 | OUTD2 | R209 | R208 | Q26-G | R77 | TP37 | Q7-G | R107 | R65 | R63 | R70 | R78 | OUTC2 | TP36 | L5 | R106 | R129 | R51 | R53 | R50 | R52 | TP34 | R180 | R182 | R181 | OUTA2 | COMP | TP32 | CN7 | CN6 | C6 | Q19 | TP33 | Q18 | C2 | TP41 | R118 | LGND | CN4 | Q17 | CN5 | C4 | C5 | Q16 | R55 | R58 | R207 | R184 | C3 | Q15 | R223 | R224 | PFC OUT | OR-G | 12VOUT | CN1 | C30 | L11 | C65 | C33 | R138 | C32 | C52 | C31 | D50 | L12 | L1 | D48 | C70 | IC20 | TP39 | OUTB2 | R86 | TP38 | OUTA1 | D32 | FB2 | L2 | R222 | C63 | R220 | R127 | OUTD1 | R31 | R123 | TP10 | R83 | R177 | IC5 | C57 | C18 | R113 | R112 | D40 | FB1 | R221 | C58 | L3 | C84 | C85 | C35 | R122 | R82 | R172 | TP44 | T6 | T5 | C101 | C66 | R116 | C98 | C97 | R190 | R192 | R124 | C73 | Q13 | Q27-G | TP23 | TP20 | TP35 | TP42 | CN10 | TP28 | L6 | TP40 | TP31 | CN8 | REPLACE ONLY WITH SAME TYPE | 250V T15AH | CAUTION
User.5: 1 | 2 | 6 | 7 | 3 | 4 | 5
User.6: 1 | 2 | 7 | 6 | 4 | 3 | 5 | IC1 | R7 | C36 | R85 | R8 | C34 | C43 | C44 | R99 | C45 | R81 | C77 | R96 | D16 | C19 | C56 | R137 | R136 | D17 | D18 | D19 | D47 | D46 | R102 | R101 | C75 | R91 | C76 | D22 | R92 | R169 | R170 | R187 | R189 | IC22 | R160 | R154 | C72 | Q8 | D14 | R186 | Q25 | Q14 | D35 | D20 | D26 | D21 | R157 | R153 | D52 | D51 | C71 | D54 | D53 | D29 | D28 | Q28 | IC13 | IC14 | D34 | R217 | R218 | R216 | Q9 | Q10 | R213 | R149 | R194 | R150 | R195 | R219 | R20 | R59 | R67 | R212 | C27 | R76 | R18 | R19 | R49 | R211 | R210 | R66 | R64 | D56 | D55 | R22 | R214 | R23 | C25 | C99 | R43 | R47 | R45 | R42 | R46 | IC8 | C22 | R57 | R56 | R60 | R61 | C100 | Q24 | C59 | Q23 | Q22 | C92 | Q21 | R202 | R203 | Q20 | R199 | R205 | C93 | R79 | R80 | D13 | R95 | R94 | R98 | D12 | D49 | C46 | C48 | R97 | C49 | C47 | C42 | R100 | R103 | IC3 | C40 | R93 | C41 | R29 | R104 | C50 | C39 | R171 | C38 | R89 | R1 | R2 | R179 | R178 | C96 | R188 | C95 | IC21 | R215 | R24 | D58 | R25 | R9 | D57 | D27 | R185 | R21 | R105 | C51 | R69 | C23 | C26 | C24 | IC10 | R48 | R54 | C21 | R44 | C20 | R62 | R75 | R6 | R200 | R201 | C94 | R204 | R206 | R90 | R227 | R228 | C102
